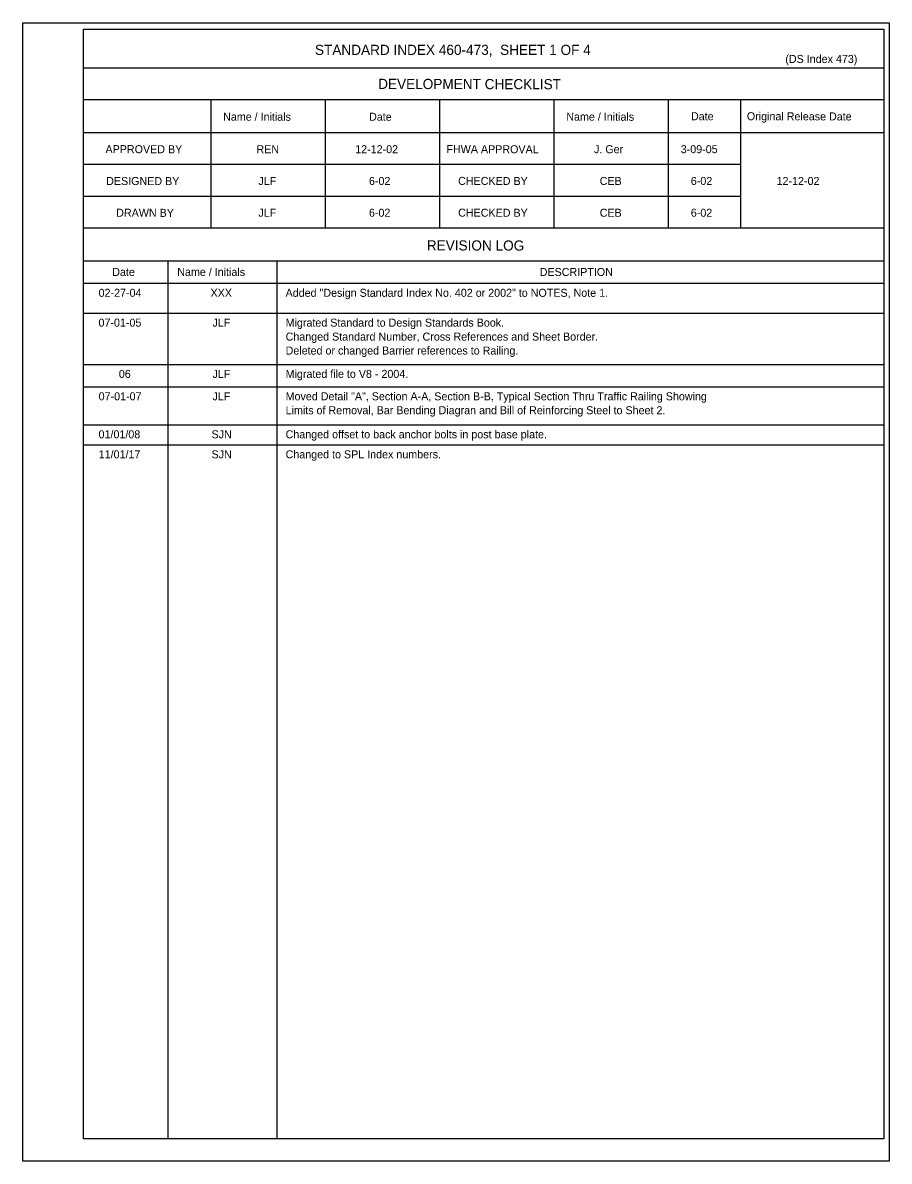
# Model space of a CAD drawing. Extents: x 21516.9 to 21586.2, y 56155.7 to 56195.
# Drawn here: x 21564.41 to 21586.23, y 56162.48 to 56191.15 of the extents above; entities that cross this region are included whole.
import ezdxf

# ---------------------------------------------------------------- set-up
doc = ezdxf.new("R2010")
doc.units = 0
for name, color, linetype in [('PlotBorder_dp', 7, 'Continuous'), ('SheetBorder_dp', 7, 'Continuous'), ('SheetLines_dp', 7, 'Continuous')]:
    doc.layers.add(name, color=color, linetype=linetype)

msp = doc.modelspace()

# ---------------------------------------------------------------- linework, layer by layer
at = {"layer": 'PlotBorder_dp'}
for p, q in [((21565.943, 56183.838), (21586.09, 56183.838)), ((21565.944, 56182.547), (21586.09, 56182.547)), ((21565.944, 56181.983), (21586.09, 56181.983)), ((21565.944, 56181.026), (21586.09, 56181.026)), ((21565.944, 56180.522), (21586.09, 56180.522)), ((21564.413, 56162.485), (21564.413, 56162.485))]:
    msp.add_line(p, q, dxfattribs=at)
msp.add_lwpolyline([(21564.413, 56191.151), (21586.226, 56191.151), (21586.226, 56162.485), (21564.413, 56162.485)], close=True, dxfattribs=at)
at = {"layer": 'SheetLines_dp'}
for p, q in [((21586.09, 56190.008), (21565.943, 56190.008)), ((21586.09, 56189.208), (21565.943, 56189.208)), ((21569.143, 56189.208), (21569.143, 56185.98)), ((21572.023, 56189.208), (21572.023, 56185.98)), ((21574.903, 56189.208), (21574.903, 56185.98)), ((21577.783, 56189.208), (21577.783, 56185.98)), ((21580.663, 56189.208), (21580.663, 56185.98)), ((21582.478, 56189.208), (21582.478, 56185.98)), ((21586.09, 56188.38), (21565.943, 56188.38)), ((21582.478, 56187.58), (21565.943, 56187.58)), ((21582.478, 56186.78), (21565.943, 56186.78)), ((21586.09, 56185.98), (21565.943, 56185.98)), ((21586.09, 56185.152), (21565.943, 56185.152)), ((21568.063, 56185.152), (21568.063, 56163.046)), ((21570.806, 56185.152), (21570.806, 56163.046)), ((21586.09, 56184.589), (21565.943, 56184.589))]:
    msp.add_line(p, q, dxfattribs=at)
msp.add_lwpolyline([(21565.943, 56190.989), (21586.09, 56190.989), (21586.09, 56163.046), (21565.943, 56163.046)], close=True, dxfattribs=at)

# ---------------------------------------------------------------- texts
at = {"layer": 'SheetBorder_dp'}
for s, height, p in [('STANDARD INDEX 460-473,  SHEET 1 OF 4', 0.256, (21571.768, 56190.341)), ('(DS Index 473)', 0.2016, (21583.611, 56190.14)), ('REN', 0.2016, (21570.295, 56187.867)), ('12-12-02', 0.2016, (21572.782, 56187.867)), ('J. Ger', 0.2016, (21578.793, 56187.867)), ('3-09-05', 0.2016, (21580.977, 56187.867)), ('JLF', 0.2016, (21570.343, 56187.067)), ('6-02', 0.2016, (21573.128, 56187.067)), ('CEB', 0.2016, (21578.937, 56187.067)), ('6-02', 0.2016, (21581.231, 56187.067)), ('12-12-02', 0.2016, (21583.39, 56187.067)), ('JLF', 0.2016, (21570.343, 56186.267)), ('6-02', 0.2016, (21573.128, 56186.267)), ('CEB', 0.2016, (21578.937, 56186.267)), ('6-02', 0.2016, (21581.231, 56186.267)), ('DESCRIPTION', 0.2016, (21577.427, 56184.775)), ('02-27-04', 0.2016, (21566.322, 56184.251)), ('XXX', 0.2016, (21569.14, 56184.251)), ('Added "Design Standard Index No. 402 or 2002" to NOTES, Note 1. ', 0.2016, (21571.029, 56184.251)), ('07-01-05', 0.2016, (21566.319, 56183.5)), ('JLF', 0.2016, (21569.19, 56183.5)), ('Migrated Standard to Design Standards Book.', 0.2016, (21571.03, 56183.5)), ('Changed Standard Number, Cross References and Sheet Border.', 0.2016, (21571.03, 56183.148)), ('Deleted or changed Barrier references to Railing.', 0.2016, (21571.03, 56182.797)), ('06', 0.2016, (21566.831, 56182.209)), ('JLF', 0.2016, (21569.19, 56182.209)), ('Migrated file to V8 - 2004.', 0.2016, (21571.03, 56182.209)), ('07-01-07', 0.2016, (21566.323, 56181.645)), ('JLF', 0.2016, (21569.19, 56181.645)), ('Moved Detail "A", Section A-A, Section B-B, Typical Section Thru Traffic Railing Showing ', 0.2016, (21571.03, 56181.645)), ('Limits of Removal, Bar Bending Diagran and Bill of Reinforcing Steel to Sheet 2.', 0.2016, (21571.03, 56181.294)), ('01/01/08', 0.2016, (21566.321, 56180.688)), ('SJN', 0.2016, (21569.165, 56180.688)), ('Changed offset to back anchor bolts in post base plate.', 0.2016, (21571.03, 56180.688)), ('11/01/17', 0.2016, (21566.325, 56180.184)), ('SJN', 0.2016, (21569.165, 56180.184)), ('Changed to SPL Index numbers.', 0.2016, (21571.03, 56180.184))]:
    msp.add_text(s, height=height, dxfattribs=at).set_placement(p)
for s, height, p in [('DEVELOPMENT CHECKLIST', 0.256, (21573.359, 56189.485)), ('Name / Initials', 0.2016, (21569.456, 56188.687)), ('Date', 0.2016, (21573.13, 56188.685)), ('Name / Initials', 0.2016, (21578.096, 56188.687)), ('Date', 0.2016, (21581.235, 56188.697)), ('Original Release Date', 0.2016, (21582.642, 56188.697)), ('APPROVED BY', 0.2016, (21566.495, 56187.869)), ('FHWA APPROVAL', 0.2016, (21575.078, 56187.869)), ('DESIGNED BY', 0.2016, (21566.512, 56187.067)), ('CHECKED BY', 0.2016, (21575.373, 56187.069)), ('DRAWN BY', 0.2016, (21566.765, 56186.267)), ('CHECKED BY', 0.2016, (21575.373, 56186.269)), ('REVISION LOG', 0.256, (21574.584, 56185.419)), ('Date', 0.2016, (21566.665, 56184.776)), ('Name / Initials', 0.2016, (21568.302, 56184.778))]:
    msp.add_text(s, height=height, rotation=359.8756, dxfattribs=at).set_placement(p)

doc.saveas('drawing.dxf')
